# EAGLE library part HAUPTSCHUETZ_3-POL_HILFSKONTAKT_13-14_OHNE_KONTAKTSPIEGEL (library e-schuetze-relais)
Hauptschütz, 3-pol. mit Hilfskontakt-Schließer ohne Kontaktspiegel
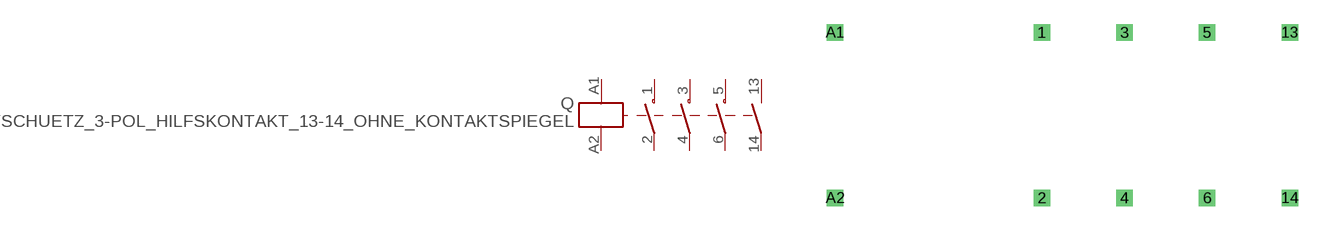
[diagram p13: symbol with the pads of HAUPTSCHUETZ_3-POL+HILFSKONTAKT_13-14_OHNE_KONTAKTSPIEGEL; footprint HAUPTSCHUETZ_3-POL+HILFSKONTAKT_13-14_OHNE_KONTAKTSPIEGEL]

Designator prefix Q

## HAUPTSCHUETZ_3-POL_HILFSKONTAKT_13-14_OHNE_KONTAKTSPIEGEL  [HAUPTSCHUETZ_3-POL+HILFSKONTAKT_13-14_OHNE_KONTAKTSPIEGEL]
1  1  pas
2  2  pas
3  3  pas
4  4  pas
5  5  pas
6  6  pas
13  7  pas
14  8  pas
A1  A1  in
A2  A2  in

## Footprint HAUPTSCHUETZ_3-POL+HILFSKONTAKT_13-14_OHNE_KONTAKTSPIEGEL (pad centres in mm)
Dummy
drill 0.5 pad 1 square: 1 2.54,2.54; 2 2.54,-7.62; 3 7.62,2.54; 4 7.62,-7.62; 5 12.7,2.54; 6 12.7,-7.62; 13 17.78,2.54; 14 17.78,-7.62; A1 -10.16,2.54; A2 -10.16,-7.62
